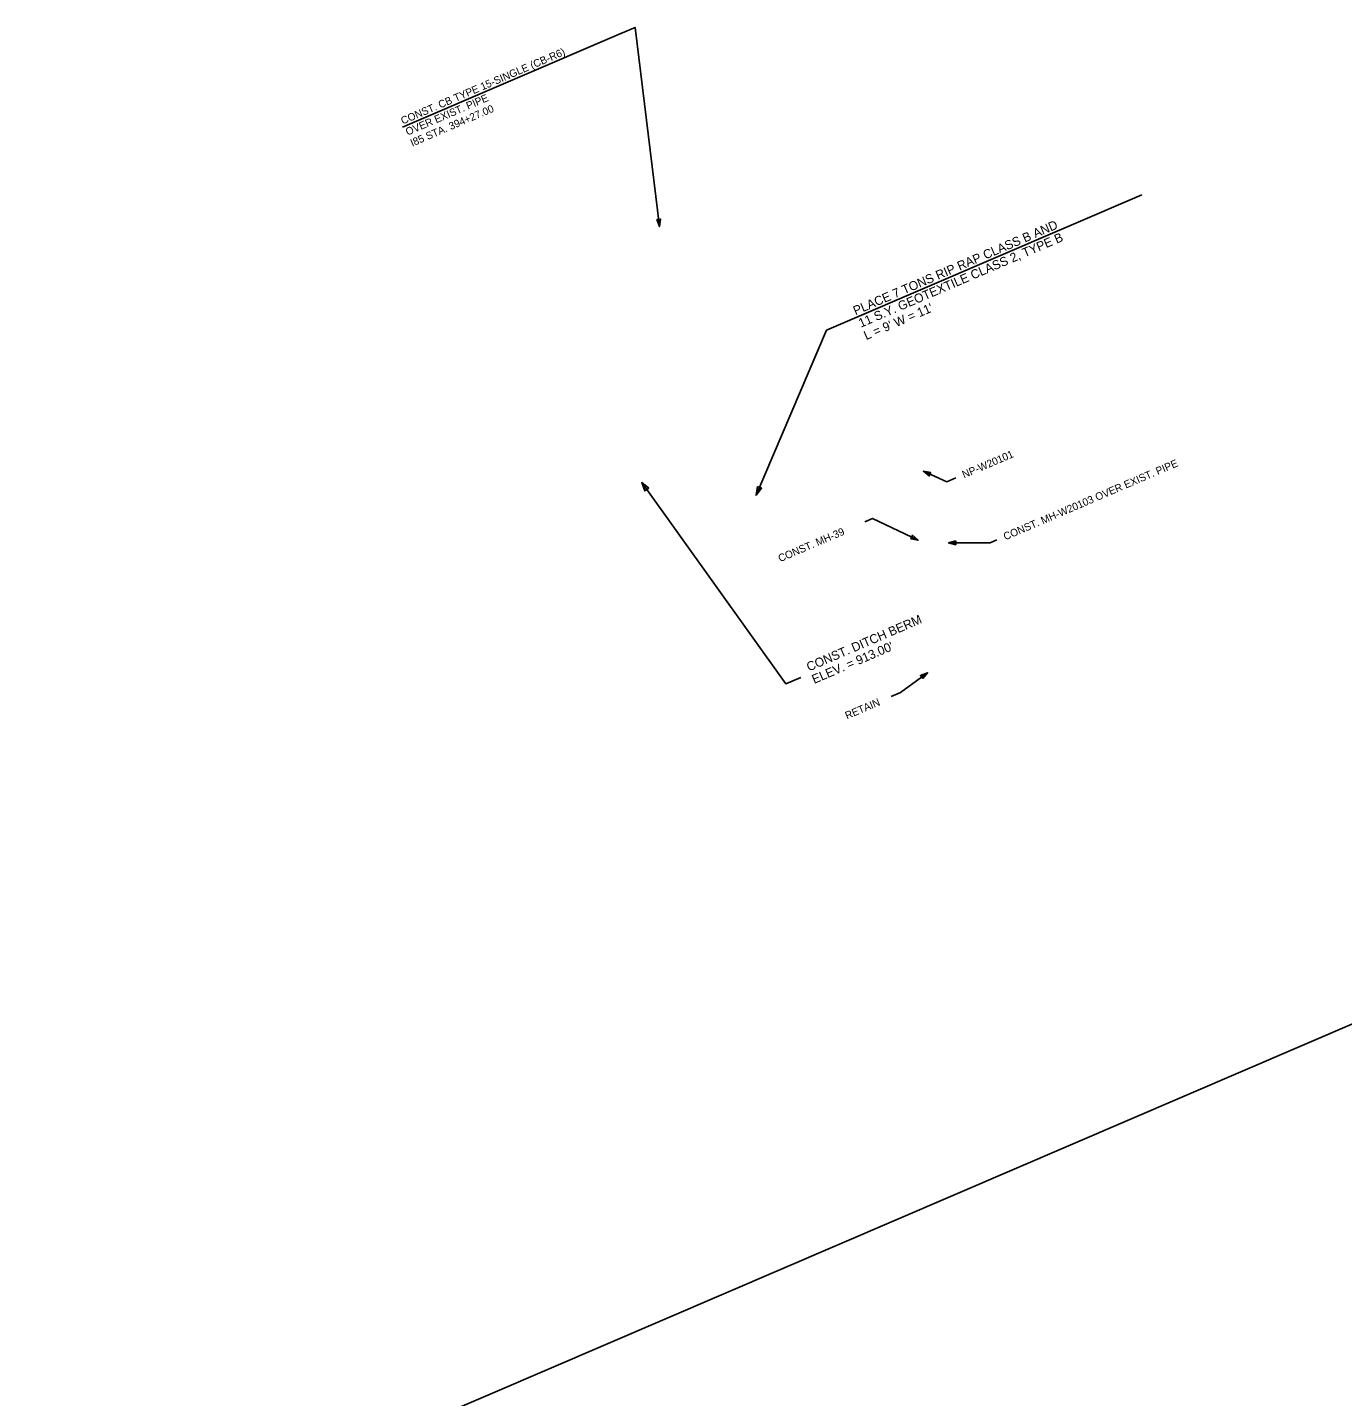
# Model space of a CAD drawing. Extents: x 1619705 to 1621490, y 1101723 to 1103701.
# Drawn here: x 1619705 to 1620580, y 1102790 to 1103701 of the extents above; entities that cross this region are included whole.
import ezdxf

# ---------------------------------------------------------------- set-up
doc = ezdxf.new("R2010")
doc.units = 0
doc.layers.add('Level 2', color=7, linetype='Continuous')
doc.layers.add('RFP', color=7, linetype='Continuous')

msp = doc.modelspace()

# ---------------------------------------------------------------- linework, layer by layer
at = {"layer": 'Level 2'}
for p, q in [((1620100.2, 1103696.93), (1619954.77, 1103634.52)), ((1620446.85, 1103589.54), (1620251, 1103505.49))]:
    msp.add_line(p, q, dxfattribs=at)
for points in [[(1620100.2, 1103696.93), (1620109.63, 1103700.98), (1620125.9, 1103568.48)], [(1620251, 1103505.49), (1620237.09, 1103499.52), (1620190.16, 1103389.67)], [(1620323.02, 1103401.2), (1620317.17, 1103398.69), (1620301.52, 1103405.69)], [(1620219.99, 1103268.51), (1620209.98, 1103264.21), (1620114.12, 1103398.16)], [(1620262.63, 1103372.09), (1620267.71, 1103374.27), (1620298.01, 1103359.81)], [(1620350.46, 1103360), (1620345.96, 1103358.07), (1620318.26, 1103358.03)], [(1620279.97, 1103255.85), (1620286.28, 1103258.55), (1620304.26, 1103271.58)]]:
    msp.add_lwpolyline(points, dxfattribs=at)
for points in [[(1620124.03, 1103573.11), (1620125.9, 1103568.48), (1620126.6, 1103573.43)], [(1620306.46, 1103404.9), (1620301.52, 1103405.69), (1620305.4, 1103402.54)], [(1620118.75, 1103394.35), (1620114.12, 1103398.16), (1620116.23, 1103392.55)], [(1620191.01, 1103395.61), (1620190.16, 1103389.67), (1620193.87, 1103394.39)], [(1620293.09, 1103360.72), (1620298.01, 1103359.81), (1620294.21, 1103363.06)], [(1620323.08, 1103359.33), (1620318.26, 1103358.03), (1620323.09, 1103356.74)], [(1620301.11, 1103267.7), (1620304.26, 1103271.58), (1620299.59, 1103269.8)]]:
    msp.add_lwpolyline(points, close=True, dxfattribs=at)
at = {"layer": 'RFP'}
msp.add_lwpolyline([(1620077.33, 1101792.57), (1621455.74, 1102384.16), (1621344.3, 1102622.52), (1621323.62, 1102755.47), (1621298.88, 1102749.66), (1621097.02, 1103220), (1620951.48, 1103157.13), (1620938.43, 1103188.78), (1619705.25, 1102659.52)], close=True, dxfattribs=at)
msp.add_lwpolyline([(1620077.33, 1101792.57), (1621455.74, 1102384.16), (1621344.3, 1102622.52), (1621323.62, 1102755.47), (1621298.88, 1102749.66), (1621097.02, 1103220), (1620951.48, 1103157.13), (1620938.43, 1103188.78), (1619705.25, 1102659.52)], close=True, dxfattribs=at)
msp.add_lwpolyline([(1620077.33, 1101792.57), (1621455.74, 1102384.16), (1621344.3, 1102622.52), (1621323.62, 1102755.47), (1621298.88, 1102749.66), (1621097.02, 1103220), (1620951.48, 1103157.13), (1620938.43, 1103188.78), (1619705.25, 1102659.52)], close=True, dxfattribs=at)
msp.add_lwpolyline([(1620077.33, 1101792.57), (1621455.74, 1102384.16), (1621344.3, 1102622.52), (1621323.62, 1102755.47), (1621298.88, 1102749.66), (1621097.02, 1103220), (1620951.48, 1103157.13), (1620938.43, 1103188.78), (1619705.25, 1102659.52)], close=True, dxfattribs=at)
msp.add_lwpolyline([(1620077.33, 1101792.57), (1621455.74, 1102384.16), (1621344.3, 1102622.52), (1621323.62, 1102755.47), (1621298.88, 1102749.66), (1621097.02, 1103220), (1620951.48, 1103157.13), (1620938.43, 1103188.78), (1619705.25, 1102659.52)], close=True, dxfattribs=at)

# ---------------------------------------------------------------- texts
at = {"layer": 'Level 2'}
for s, height, p in [('CONST. CB TYPE 15-SINGLE (CB-R6)', 5, (1619955.09, 1103636.29)), ('OVER EXIST. PIPE', 5, (1619958.25, 1103628.94)), ('I85 STA. 394+27.00', 5, (1619961.4, 1103621.59)), ('PLACE 7 TONS RIP RAP CLASS B AND', 6, (1620256.34, 1103509.41)), ('11 S.Y. GEOTEXTILE CLASS 2, TYPE B', 6, (1620259.89, 1103501.14)), ("L = 9' W = 11'", 6, (1620263.44, 1103492.87)), ('NP-W20101', 5, (1620328.6, 1103400.88)), ('CONST. MH-W20103 OVER EXIST. PIPE', 5, (1620356.04, 1103359.67)), ('CONST. MH-39', 5, (1620206.2, 1103345.15)), ('CONST. DITCH BERM', 6, (1620225.33, 1103272.43)), ("ELEV. = 913.00'", 6, (1620228.88, 1103264.16)), ('RETAIN', 5, (1620250.68, 1103240.55))]:
    msp.add_text(s, height=height, rotation=23.22835, dxfattribs=at).set_placement(p)

doc.saveas('drawing.dxf')
